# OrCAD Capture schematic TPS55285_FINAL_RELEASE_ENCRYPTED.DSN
size A
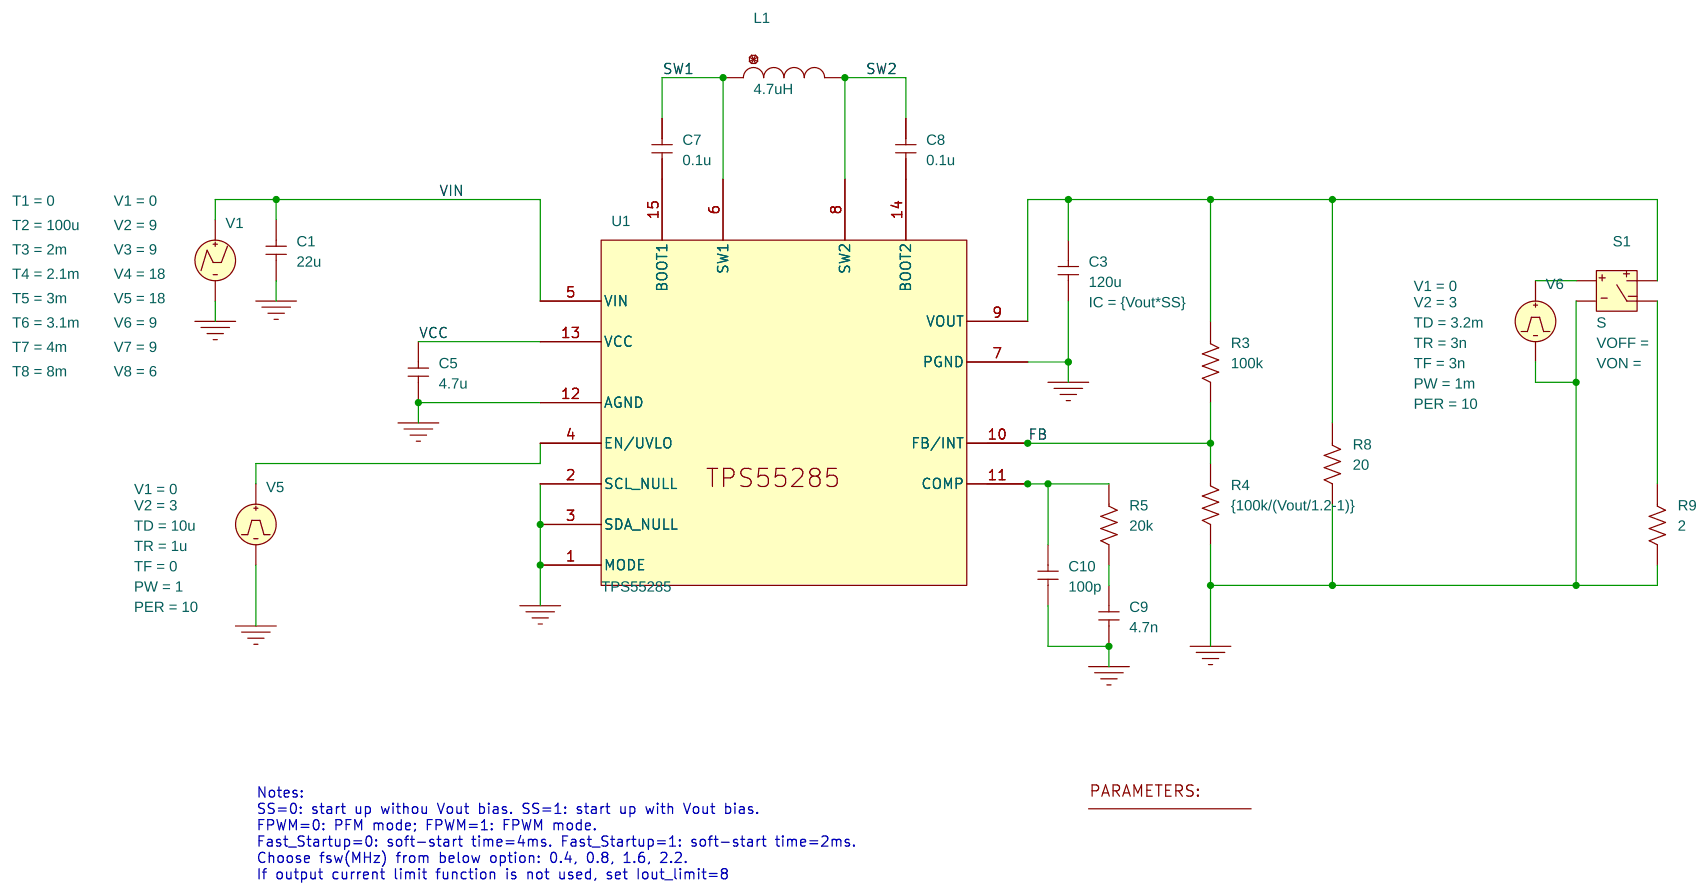
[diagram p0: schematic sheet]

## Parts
1  PARAM
C1  22u  [cap196]
C3  120u  [cap196]
C5  4.7u  [cap196]
C7  0.1u  [cap196]
C8  0.1u  [cap196]
C9  4.7n  [cap196]
C10  100p  [cap196]
L1  4.7uH  [DISC350x175LS200x100034]
R3  100k  [AXRC05]
R4  {100k/(Vout/1.2-1)}  [AXRC05]
R5  20k  [AXRC05]
R8  20  [AXRC05]
R9  2  [AXRC05]
S1  S
U1  TPS55285
V1  VPWL
V5  VPULSE
V6  VPULSE

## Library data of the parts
1 = PARAM: Fast_Startup: 0; Fsw: 0.4; Iout_limit: 5; SS: 0; VIN: 5; VOUT: 9
C1 C5 C7-C10 = C
C3 = C: IC: {Vout*SS}
L1 = L
R3-R5 R8 R9 = R
S1 = S: RON: 1.0m
U1 = TPS55285_SYMBOL_2
V1 = VPWL: T1: 0; T2: 100u; T3: 2m; T4: 2.1m; T5: 3m; T6: 3.1m; T7: 4m; T8: 8m; V1: 0; V2: 9; V3: 9; V4: 18; V5: 18; V6: 9; V7: 9; V8: 6
V5 = VPULSE: PER: 10; PW: 1; TD: 10u; TF: 0; TR: 1u; V1: 0; V2: 3
V6 = VPULSE: PER: 10; PW: 1m; TD: 3.2m; TF: 3n; TR: 3n; V1: 0; V2: 3

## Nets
VCC: C5.2 U1.13(VCC)
VIN: C1.2 U1.5(VIN) V1.1(+)
0: C1.1 C3.1 C5.1 C9.1 C10.1 R4.2 R8.2 R9.2 S1.1(2) U1.1(MODE) U1.2(SCL_NULL) U1.3(SDA_NULL) U1.7(PGND) U1.12(AGND) V1.2(-) V5.2(-) V6.2(-)
FB: R3.2 R4.1 U1.10(FB/INT)
SW1: C7.2 L1.1 U1.6(SW1)
SW2: C8.2 L1.2 U1.8(SW2)
N16773185: C3.2 R3.1 R8.1 S1.2(3) U1.9(VOUT)
N16773353: S1.0(1) V6.1(+)
N16773447: R9.1 S1.3(4)
N16773527: U1.4(EN/UVLO) V5.1(+)
N16773603: C10.2 R5.1 U1.11(COMP)
N16773757: C9.2 R5.2
N16775968: C7.1 U1.15(BOOT1)
N16775969: C8.1 U1.14(BOOT2)

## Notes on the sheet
- Notes:
  SS=0: start up withou Vout bias. SS=1: start up with Vout bias.
  FPWM=0: PFM mode; FPWM=1: FPWM mode.
  Fast_Startup=0: soft-start time=4ms. Fast_Startup=1: soft-start time=2ms.
  Choose fsw(MHz) from below option: 0.4, 0.8, 1.6, 2.2.
  If output current limit function is not used, set Iout_limit=8
